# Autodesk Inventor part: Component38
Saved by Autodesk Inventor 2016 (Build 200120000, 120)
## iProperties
Created: 2016-09
Part Number: Component38
Material: Generic
Document SubType Name: Modeling
Designer: Administrator
Appearance: Generic
Author: Administrator
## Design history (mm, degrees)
feature "Body4"
feature "Body1"
feature "Body3"
feature "Body2"
body "Solid1"
body "Solid2"
body "Solid3"
body "Solid4"
